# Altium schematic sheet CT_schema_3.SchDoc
size 144 x 123 mm
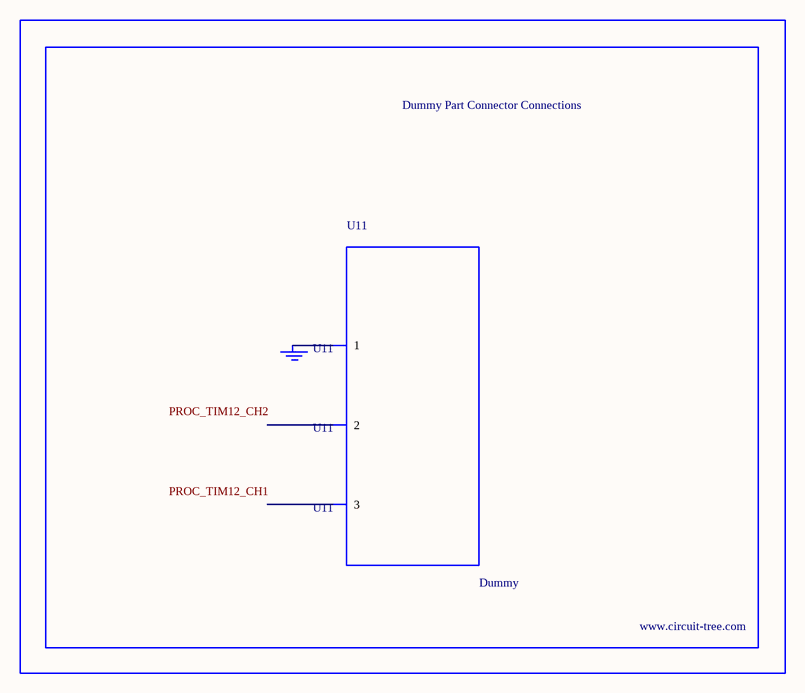
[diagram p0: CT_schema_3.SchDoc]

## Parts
BORDER2  (no value)
GND_INSTANCE_2_0  (no value)
U11  Dummy  [DUMMY_PACKAGE_98]

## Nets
NetGND_INSTANCE_2_0_0: GND_INSTANCE_2_0.0(GND) U11.1

Not connected (* = marked no-connect by the designer): U11 2 3

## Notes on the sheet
- Labels drawn without touching a wire or pin: PROC_TIM12_CH1, PROC_TIM12_CH2

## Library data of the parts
BORDER2 = BORDER_PAGE2
GND_INSTANCE_2_0 = GND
